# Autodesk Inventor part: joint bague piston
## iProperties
Created: 2002-03
Part Number: joint bague piston
Material: Par défaut
Document SubType Name: Modélisation
Designer: User
Control State: 0
Master: False
Checked Out: False
Shininess: 20.0
Length Units: 11269
Angle Units: 11279
Time Units: 11290
Mass Units: 11283
Length Display Precision: 3
Angle Display Precision: 2
Density: 0.0
Volumn: 0.0
Area: 0.0
PropertySet Name: Model Information
Author: User
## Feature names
1. Révolution1 [Revolution]
